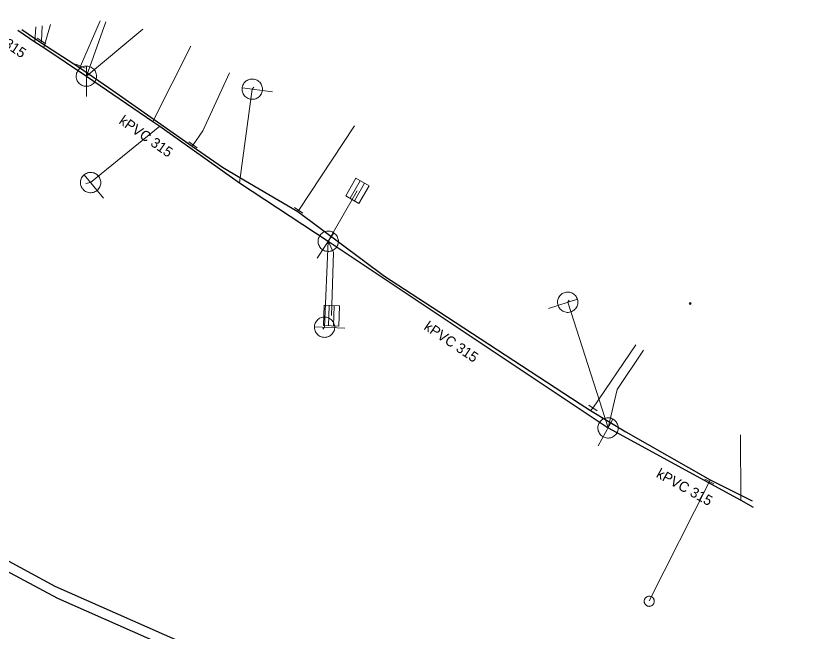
# Model space of a CAD drawing. Extents: x -783064 to -782702, y -1007904 to -1007145.
# Drawn here: x -782859.9 to -782780.5, y -1007215.4 to -1007154.7 of the extents above; entities that cross this region are included whole.
import ezdxf

# ---------------------------------------------------------------- set-up
doc = ezdxf.new("R2010")
doc.units = 0
doc.header["$LTSCALE"] = 0.4
doc.header["$PDMODE"] = 32
doc.header["$PDSIZE"] = 0.2
for name, color, linetype, lineweight in [('1', 7, 'Continuous', 13), ('11', 7, 'Continuous', 13), ('13', 7, 'Continuous', 13), ('14', 7, 'Continuous', 13), ('17', 7, 'Continuous', 25), ('22', 7, 'Continuous', 13), ('23', 7, 'Continuous', 13), ('34', 7, 'Continuous', 13)]:
    doc.layers.add(name, color=color, linetype=linetype, lineweight=lineweight)

msp = doc.modelspace()

# ---------------------------------------------------------------- linework, layer by layer
at = {"layer": '1'}
msp.add_point((-782793.51, -1007183.009), dxfattribs=at)
at = {"layer": '11'}
for p, q in [((-782851.068, -1007155.243), (-782852.989, -1007160.6)), ((-782857.952, -1007155.75), (-782858.07, -1007157.21)), ((-782856.506, -1007155.499), (-782857.17, -1007157.77)), ((-782847.429, -1007155.953), (-782852.989, -1007160.6)), ((-782842.69, -1007157.63), (-782846.434, -1007165.081)), ((-782836.5, -1007161.69), (-782836.647, -1007161.879)), ((-782836.647, -1007161.879), (-782837.899, -1007171.13)), ((-782852.569, -1007171.09), (-782845.765, -1007165.537)), ((-782853.039, -1007171.19), (-782852.569, -1007171.09)), ((-782826.307, -1007171.904), (-782829.169, -1007176.88)), ((-782829.529, -1007185.35), (-782829.169, -1007176.88)), ((-782805.43, -1007182.7), (-782805.579, -1007182.886)), ((-782805.579, -1007182.886), (-782801.609, -1007195.279)), ((-782829.704, -1007185.555), (-782829.529, -1007185.35)), ((-782788.567, -1007195.961), (-782788.533, -1007202.406))]:
    msp.add_line(p, q, dxfattribs=at)
for points in [[(-782828.847, -1007184.207), (-782828.635, -1007177.99), (-782829.169, -1007176.88)], [(-782798.12, -1007187.6), (-782800.719, -1007191.48), (-782801.609, -1007195.279)]]:
    msp.add_lwpolyline(points, dxfattribs=at)
at = {"layer": '13'}
for p, q in [((-782853.579, -1007159.609), (-782851.617, -1007155.136)), ((-782857.399, -1007157.139), (-782857.358, -1007155.647)), ((-782832.07, -1007173.819), (-782826.57, -1007165.49)), ((-782803.099, -1007193.329), (-782798.879, -1007187.09)), ((-782791.62, -1007200.559), (-782797.559, -1007212.339))]:
    msp.add_line(p, q, dxfattribs=at)
msp.add_lwpolyline([(-782842.472, -1007167.376), (-782841.51, -1007166), (-782838.899, -1007160.26)], dxfattribs=at)
at = {"layer": '14'}
for p, q in [((-782857.48, -1007157.266), (-782857.399, -1007157.139)), ((-782853.666, -1007159.732), (-782853.579, -1007159.609)), ((-782842.559, -1007167.5), (-782842.472, -1007167.376)), ((-782832.151, -1007173.945), (-782832.07, -1007173.819)), ((-782803.32, -1007193.55), (-782803.099, -1007193.329)), ((-782791.539, -1007200.39), (-782791.62, -1007200.559))]:
    msp.add_line(p, q, dxfattribs=at)
at = {"layer": '14', "lineweight": 25}
msp.add_line((-782829.169, -1007176.88), (-782801.609, -1007195.279), dxfattribs=at)
for points in [[(-782859.737, -1007156.06), (-782858.07, -1007157.21), (-782857.17, -1007157.77), (-782852.989, -1007160.6)], [(-782852.989, -1007160.6), (-782846.434, -1007165.081), (-782845.765, -1007165.537), (-782837.899, -1007171.13), (-782829.169, -1007176.88)], [(-782801.609, -1007195.279), (-782788.533, -1007202.406), (-782787.302, -1007203.076)]]:
    msp.add_lwpolyline(points, dxfattribs=at)
at = {"layer": '17'}
for points in [[(-782859.332, -1007155.99), (-782857.48, -1007157.266), (-782853.666, -1007159.732), (-782850.388, -1007162.024), (-782842.559, -1007167.5), (-782839.596, -1007169.572), (-782837.872, -1007170.585), (-782832.151, -1007173.945), (-782823.609, -1007180.33), (-782818.278, -1007183.806), (-782804.359, -1007192.92), (-782803.32, -1007193.55), (-782799.87, -1007195.68), (-782791.539, -1007200.39), (-782787.409, -1007202.472)], [(-782780.739, -1007239.982), (-782822.337, -1007225.824), (-782856.072, -1007210.901), (-782877.582, -1007199.233), (-782894.804, -1007187.137)], [(-782894.804, -1007187.137), (-782878.263, -1007200.064), (-782855.822, -1007212.077), (-782822.195, -1007226.94), (-782780.544, -1007241.082)]]:
    msp.add_lwpolyline(points, dxfattribs=at)
at = {"layer": '22'}
for p, q in [((-782852.989, -1007162.6), (-782852.988, -1007159.6)), ((-782834.664, -1007162.147), (-782837.637, -1007161.744)), ((-782851.304, -1007172.639), (-782853.2, -1007170.315)), ((-782826.013, -1007170.906), (-782827.011, -1007172.639)), ((-782825.58, -1007171.155), (-782826.577, -1007172.889)), ((-782830.269, -1007178.55), (-782828.619, -1007176.045)), ((-782807.484, -1007183.496), (-782804.627, -1007182.581)), ((-782829.137, -1007185.208), (-782829.069, -1007183.209)), ((-782828.638, -1007185.225), (-782828.569, -1007183.226)), ((-782827.53, -1007185.434), (-782830.527, -1007185.307)), ((-782802.566, -1007197.035), (-782801.13, -1007194.401))]:
    msp.add_line(p, q, dxfattribs=at)
for points in [[(-782851.989, -1007160.6), (-782851.994, -1007160.491), (-782852.012, -1007160.383), (-782852.042, -1007160.277), (-782852.082, -1007160.176), (-782852.134, -1007160.079), (-782852.196, -1007159.989), (-782852.268, -1007159.906), (-782852.348, -1007159.832), (-782852.436, -1007159.766), (-782852.53, -1007159.711), (-782852.63, -1007159.666), (-782852.735, -1007159.633), (-782852.842, -1007159.611), (-782852.951, -1007159.601), (-782853.061, -1007159.603), (-782853.169, -1007159.617), (-782853.276, -1007159.642), (-782853.379, -1007159.679), (-782853.477, -1007159.728), (-782853.569, -1007159.786), (-782853.655, -1007159.855), (-782853.732, -1007159.932), (-782853.801, -1007160.018), (-782853.86, -1007160.11), (-782853.908, -1007160.208), (-782853.945, -1007160.311), (-782853.971, -1007160.418), (-782853.985, -1007160.526), (-782853.988, -1007160.636), (-782853.978, -1007160.745), (-782853.957, -1007160.852), (-782853.923, -1007160.956), (-782853.879, -1007161.056), (-782853.824, -1007161.151), (-782853.758, -1007161.239), (-782853.684, -1007161.319), (-782853.601, -1007161.391), (-782853.511, -1007161.453), (-782853.415, -1007161.505), (-782853.313, -1007161.546), (-782853.208, -1007161.576), (-782853.1, -1007161.594), (-782852.99, -1007161.6), (-782852.881, -1007161.594), (-782852.773, -1007161.576), (-782852.668, -1007161.547), (-782852.566, -1007161.506), (-782852.469, -1007161.454), (-782852.379, -1007161.392), (-782852.296, -1007161.321), (-782852.221, -1007161.241), (-782852.156, -1007161.153), (-782852.1, -1007161.059), (-782852.056, -1007160.959), (-782852.022, -1007160.855), (-782852, -1007160.747), (-782851.99, -1007160.638)], [(-782836.512, -1007160.888), (-782836.621, -1007160.879), (-782836.73, -1007160.882), (-782836.839, -1007160.898), (-782836.945, -1007160.924), (-782837.048, -1007160.962), (-782837.145, -1007161.012), (-782837.237, -1007161.072), (-782837.321, -1007161.141), (-782837.398, -1007161.22), (-782837.466, -1007161.305), (-782837.524, -1007161.399), (-782837.57, -1007161.498), (-782837.606, -1007161.601), (-782837.631, -1007161.708), (-782837.644, -1007161.817), (-782837.644, -1007161.926), (-782837.634, -1007162.035), (-782837.611, -1007162.143), (-782837.576, -1007162.246), (-782837.531, -1007162.345), (-782837.474, -1007162.44), (-782837.408, -1007162.526), (-782837.332, -1007162.606), (-782837.249, -1007162.677), (-782837.158, -1007162.738), (-782837.061, -1007162.788), (-782836.958, -1007162.828), (-782836.853, -1007162.857), (-782836.744, -1007162.873), (-782836.635, -1007162.878), (-782836.526, -1007162.872), (-782836.418, -1007162.852), (-782836.313, -1007162.822), (-782836.212, -1007162.78), (-782836.116, -1007162.726), (-782836.027, -1007162.664), (-782835.944, -1007162.591), (-782835.871, -1007162.51), (-782835.806, -1007162.422), (-782835.752, -1007162.327), (-782835.708, -1007162.226), (-782835.676, -1007162.122), (-782835.655, -1007162.014), (-782835.646, -1007161.905), (-782835.65, -1007161.795), (-782835.665, -1007161.687), (-782835.691, -1007161.581), (-782835.73, -1007161.478), (-782835.779, -1007161.38), (-782835.839, -1007161.289), (-782835.908, -1007161.203), (-782835.986, -1007161.127), (-782836.072, -1007161.059), (-782836.165, -1007161.002), (-782836.264, -1007160.954), (-782836.368, -1007160.918), (-782836.474, -1007160.894)], [(-782851.793, -1007170.458), (-782851.867, -1007170.377), (-782851.949, -1007170.305), (-782852.04, -1007170.242), (-782852.134, -1007170.189), (-782852.236, -1007170.146), (-782852.341, -1007170.116), (-782852.449, -1007170.097), (-782852.558, -1007170.09), (-782852.668, -1007170.095), (-782852.775, -1007170.112), (-782852.881, -1007170.14), (-782852.984, -1007170.181), (-782853.08, -1007170.231), (-782853.171, -1007170.293), (-782853.255, -1007170.364), (-782853.33, -1007170.443), (-782853.397, -1007170.53), (-782853.453, -1007170.624), (-782853.498, -1007170.724), (-782853.533, -1007170.827), (-782853.556, -1007170.934), (-782853.567, -1007171.043), (-782853.566, -1007171.153), (-782853.554, -1007171.262), (-782853.529, -1007171.368), (-782853.492, -1007171.471), (-782853.445, -1007171.57), (-782853.387, -1007171.663), (-782853.319, -1007171.749), (-782853.243, -1007171.828), (-782853.159, -1007171.897), (-782853.067, -1007171.956), (-782852.969, -1007172.006), (-782852.867, -1007172.045), (-782852.76, -1007172.071), (-782852.652, -1007172.086), (-782852.542, -1007172.09), (-782852.433, -1007172.081), (-782852.326, -1007172.06), (-782852.221, -1007172.028), (-782852.121, -1007171.984), (-782852.026, -1007171.93), (-782851.937, -1007171.865), (-782851.856, -1007171.792), (-782851.784, -1007171.709), (-782851.721, -1007171.621), (-782851.668, -1007171.524), (-782851.625, -1007171.423), (-782851.595, -1007171.318), (-782851.575, -1007171.21), (-782851.568, -1007171.101), (-782851.573, -1007170.992), (-782851.589, -1007170.883), (-782851.618, -1007170.778), (-782851.658, -1007170.676), (-782851.709, -1007170.578), (-782851.77, -1007170.488)], [(-782825.147, -1007171.404), (-782826.144, -1007173.138), (-782827.444, -1007172.39), (-782826.447, -1007170.656)], [(-782828.334, -1007177.43), (-782828.279, -1007177.336), (-782828.234, -1007177.236), (-782828.201, -1007177.131), (-782828.179, -1007177.024), (-782828.169, -1007176.915), (-782828.171, -1007176.805), (-782828.186, -1007176.696), (-782828.212, -1007176.591), (-782828.249, -1007176.487), (-782828.297, -1007176.389), (-782828.356, -1007176.297), (-782828.426, -1007176.212), (-782828.503, -1007176.134), (-782828.588, -1007176.066), (-782828.681, -1007176.007), (-782828.779, -1007175.959), (-782828.882, -1007175.921), (-782828.989, -1007175.896), (-782829.098, -1007175.883), (-782829.206, -1007175.881), (-782829.316, -1007175.891), (-782829.423, -1007175.913), (-782829.528, -1007175.947), (-782829.627, -1007175.991), (-782829.721, -1007176.046), (-782829.809, -1007176.112), (-782829.89, -1007176.187), (-782829.961, -1007176.27), (-782830.023, -1007176.36), (-782830.074, -1007176.457), (-782830.116, -1007176.558), (-782830.145, -1007176.663), (-782830.163, -1007176.771), (-782830.169, -1007176.881), (-782830.162, -1007176.991), (-782830.145, -1007177.098), (-782830.115, -1007177.204), (-782830.074, -1007177.305), (-782830.022, -1007177.401), (-782829.96, -1007177.492), (-782829.889, -1007177.575), (-782829.808, -1007177.649), (-782829.72, -1007177.714), (-782829.625, -1007177.769), (-782829.525, -1007177.814), (-782829.422, -1007177.847), (-782829.314, -1007177.869), (-782829.204, -1007177.879), (-782829.095, -1007177.877), (-782828.987, -1007177.863), (-782828.88, -1007177.838), (-782828.777, -1007177.8), (-782828.679, -1007177.752), (-782828.587, -1007177.693), (-782828.501, -1007177.625), (-782828.424, -1007177.547), (-782828.355, -1007177.461)], [(-782805.274, -1007183.838), (-782805.172, -1007183.799), (-782805.075, -1007183.749), (-782804.983, -1007183.688), (-782804.899, -1007183.619), (-782804.822, -1007183.54), (-782804.755, -1007183.454), (-782804.698, -1007183.36), (-782804.652, -1007183.261), (-782804.616, -1007183.157), (-782804.593, -1007183.051), (-782804.58, -1007182.942), (-782804.581, -1007182.832), (-782804.593, -1007182.723), (-782804.616, -1007182.616), (-782804.652, -1007182.512), (-782804.698, -1007182.413), (-782804.755, -1007182.319), (-782804.821, -1007182.232), (-782804.898, -1007182.154), (-782804.981, -1007182.084), (-782805.073, -1007182.023), (-782805.17, -1007181.973), (-782805.273, -1007181.934), (-782805.378, -1007181.906), (-782805.486, -1007181.89), (-782805.596, -1007181.886), (-782805.706, -1007181.894), (-782805.813, -1007181.914), (-782805.918, -1007181.945), (-782806.019, -1007181.988), (-782806.114, -1007182.041), (-782806.203, -1007182.105), (-782806.285, -1007182.177), (-782806.358, -1007182.259), (-782806.422, -1007182.348), (-782806.476, -1007182.443), (-782806.519, -1007182.544), (-782806.551, -1007182.649), (-782806.571, -1007182.756), (-782806.579, -1007182.866), (-782806.575, -1007182.975), (-782806.559, -1007183.083), (-782806.532, -1007183.19), (-782806.493, -1007183.292), (-782806.443, -1007183.389), (-782806.383, -1007183.48), (-782806.313, -1007183.565), (-782806.234, -1007183.641), (-782806.147, -1007183.708), (-782806.054, -1007183.766), (-782805.955, -1007183.813), (-782805.851, -1007183.848), (-782805.745, -1007183.872), (-782805.636, -1007183.884), (-782805.527, -1007183.884), (-782805.417, -1007183.872), (-782805.31, -1007183.849)], [(-782829.637, -1007185.191), (-782829.569, -1007183.192), (-782828.07, -1007183.243), (-782828.138, -1007185.242)], [(-782829.486, -1007184.35), (-782829.595, -1007184.352), (-782829.703, -1007184.365), (-782829.811, -1007184.391), (-782829.913, -1007184.426), (-782830.012, -1007184.474), (-782830.105, -1007184.532), (-782830.191, -1007184.601), (-782830.268, -1007184.677), (-782830.338, -1007184.763), (-782830.397, -1007184.854), (-782830.446, -1007184.952), (-782830.483, -1007185.056), (-782830.51, -1007185.162), (-782830.525, -1007185.27), (-782830.527, -1007185.38), (-782830.518, -1007185.489), (-782830.497, -1007185.597), (-782830.465, -1007185.701), (-782830.42, -1007185.801), (-782830.366, -1007185.895), (-782830.301, -1007185.984), (-782830.227, -1007186.064), (-782830.144, -1007186.137), (-782830.055, -1007186.2), (-782829.959, -1007186.252), (-782829.857, -1007186.293), (-782829.752, -1007186.324), (-782829.644, -1007186.342), (-782829.534, -1007186.349), (-782829.425, -1007186.344), (-782829.317, -1007186.327), (-782829.212, -1007186.298), (-782829.11, -1007186.258), (-782829.013, -1007186.207), (-782828.922, -1007186.145), (-782828.839, -1007186.074), (-782828.764, -1007185.995), (-782828.698, -1007185.907), (-782828.642, -1007185.814), (-782828.597, -1007185.713), (-782828.562, -1007185.61), (-782828.54, -1007185.503), (-782828.529, -1007185.393), (-782828.53, -1007185.284), (-782828.544, -1007185.175), (-782828.568, -1007185.069), (-782828.605, -1007184.965), (-782828.653, -1007184.866), (-782828.711, -1007184.774), (-782828.778, -1007184.688), (-782828.855, -1007184.609), (-782828.94, -1007184.541), (-782829.032, -1007184.481), (-782829.13, -1007184.433), (-782829.232, -1007184.394), (-782829.339, -1007184.368), (-782829.448, -1007184.353)], [(-782800.731, -1007195.757), (-782800.684, -1007195.659), (-782800.648, -1007195.555), (-782800.624, -1007195.448), (-782800.61, -1007195.34), (-782800.61, -1007195.23), (-782800.621, -1007195.121), (-782800.644, -1007195.014), (-782800.679, -1007194.911), (-782800.725, -1007194.811), (-782800.781, -1007194.717), (-782800.847, -1007194.63), (-782800.924, -1007194.551), (-782801.007, -1007194.48), (-782801.098, -1007194.419), (-782801.196, -1007194.369), (-782801.297, -1007194.329), (-782801.403, -1007194.3), (-782801.511, -1007194.283), (-782801.621, -1007194.279), (-782801.729, -1007194.286), (-782801.838, -1007194.306), (-782801.942, -1007194.336), (-782802.044, -1007194.379), (-782802.14, -1007194.431), (-782802.229, -1007194.495), (-782802.311, -1007194.567), (-782802.385, -1007194.649), (-782802.449, -1007194.737), (-782802.503, -1007194.833), (-782802.547, -1007194.933), (-782802.579, -1007195.037), (-782802.599, -1007195.145), (-782802.608, -1007195.253), (-782802.606, -1007195.363), (-782802.59, -1007195.472), (-782802.563, -1007195.578), (-782802.525, -1007195.681), (-782802.475, -1007195.778), (-782802.416, -1007195.87), (-782802.346, -1007195.955), (-782802.268, -1007196.031), (-782802.182, -1007196.099), (-782802.088, -1007196.157), (-782801.99, -1007196.203), (-782801.886, -1007196.239), (-782801.78, -1007196.264), (-782801.671, -1007196.277), (-782801.561, -1007196.278), (-782801.452, -1007196.266), (-782801.345, -1007196.244), (-782801.241, -1007196.209), (-782801.142, -1007196.163), (-782801.048, -1007196.107), (-782800.961, -1007196.041), (-782800.882, -1007195.966), (-782800.811, -1007195.881), (-782800.75, -1007195.79)]]:
    msp.add_lwpolyline(points, close=True, dxfattribs=at)
at = {"layer": '23'}
for points in [[(-782797.328, -1007211.92), (-782797.377, -1007211.899), (-782797.427, -1007211.884), (-782797.478, -1007211.875), (-782797.53, -1007211.87), (-782797.582, -1007211.871), (-782797.635, -1007211.878), (-782797.685, -1007211.889), (-782797.734, -1007211.906), (-782797.782, -1007211.928), (-782797.827, -1007211.955), (-782797.869, -1007211.986), (-782797.908, -1007212.022), (-782797.942, -1007212.061), (-782797.971, -1007212.103), (-782797.997, -1007212.149), (-782798.018, -1007212.199), (-782798.034, -1007212.247), (-782798.044, -1007212.3), (-782798.049, -1007212.35), (-782798.048, -1007212.403), (-782798.041, -1007212.456), (-782798.029, -1007212.507), (-782798.012, -1007212.557), (-782797.991, -1007212.604), (-782797.964, -1007212.648), (-782797.931, -1007212.69), (-782797.897, -1007212.728), (-782797.857, -1007212.763), (-782797.814, -1007212.792), (-782797.769, -1007212.818), (-782797.721, -1007212.839), (-782797.67, -1007212.854), (-782797.618, -1007212.865), (-782797.567, -1007212.87), (-782797.516, -1007212.867), (-782797.463, -1007212.861), (-782797.412, -1007212.85), (-782797.362, -1007212.833), (-782797.315, -1007212.811)], [(-782798.044, -1007212.3), (-782798.049, -1007212.35), (-782798.048, -1007212.403), (-782798.041, -1007212.456), (-782798.029, -1007212.507), (-782798.012, -1007212.557), (-782797.991, -1007212.604), (-782797.964, -1007212.648), (-782797.931, -1007212.69), (-782797.897, -1007212.728), (-782797.857, -1007212.763), (-782797.814, -1007212.792), (-782797.769, -1007212.818), (-782797.721, -1007212.839), (-782797.67, -1007212.854), (-782797.618, -1007212.865), (-782797.567, -1007212.87), (-782797.516, -1007212.867), (-782797.463, -1007212.861), (-782797.412, -1007212.85), (-782797.362, -1007212.833), (-782797.315, -1007212.811), (-782797.27, -1007212.785), (-782797.228, -1007212.753), (-782797.189, -1007212.718), (-782797.155, -1007212.677), (-782797.126, -1007212.635), (-782797.1, -1007212.59), (-782797.08, -1007212.542), (-782797.064, -1007212.492), (-782797.053, -1007212.44), (-782797.05, -1007212.388), (-782797.05, -1007212.335), (-782797.056, -1007212.284), (-782797.069, -1007212.233), (-782797.084, -1007212.183), (-782797.107, -1007212.136), (-782797.134, -1007212.09), (-782797.165, -1007212.048), (-782797.201, -1007212.01)], [(-782797.315, -1007212.811), (-782797.27, -1007212.785), (-782797.228, -1007212.753), (-782797.189, -1007212.718), (-782797.155, -1007212.677), (-782797.126, -1007212.635), (-782797.1, -1007212.59), (-782797.08, -1007212.542), (-782797.064, -1007212.492), (-782797.053, -1007212.44), (-782797.05, -1007212.388), (-782797.05, -1007212.335), (-782797.056, -1007212.284), (-782797.069, -1007212.233), (-782797.084, -1007212.183), (-782797.107, -1007212.136), (-782797.134, -1007212.09), (-782797.165, -1007212.048), (-782797.201, -1007212.01), (-782797.241, -1007211.977), (-782797.283, -1007211.947), (-782797.328, -1007211.92), (-782797.377, -1007211.899), (-782797.427, -1007211.884), (-782797.478, -1007211.875), (-782797.53, -1007211.87), (-782797.582, -1007211.871), (-782797.635, -1007211.878), (-782797.685, -1007211.889), (-782797.734, -1007211.906), (-782797.782, -1007211.928), (-782797.827, -1007211.955), (-782797.869, -1007211.986), (-782797.908, -1007212.022), (-782797.942, -1007212.061), (-782797.971, -1007212.103), (-782797.997, -1007212.149), (-782798.018, -1007212.199), (-782798.034, -1007212.247), (-782798.044, -1007212.3)], [(-782797.201, -1007212.01), (-782797.241, -1007211.977), (-782797.283, -1007211.947), (-782797.328, -1007211.92)]]:
    msp.add_lwpolyline(points, dxfattribs=at)
at = {"layer": '34'}
for p, q in [((-782857.819, -1007156.869), (-782856.978, -1007157.409)), ((-782854.037, -1007159.408), (-782853.121, -1007159.81)), ((-782842.882, -1007167.089), (-782842.062, -1007167.662)), ((-782832.487, -1007173.543), (-782831.653, -1007174.094)), ((-782803.513, -1007193.049), (-782802.685, -1007193.609)), ((-782792.066, -1007200.334), (-782791.173, -1007200.784))]:
    msp.add_line(p, q, dxfattribs=at)

# ---------------------------------------------------------------- texts
at = {"layer": '1'}
for rotation, p in [(326, (-782864.348, -1007155.5)), (325, (-782849.86, -1007165.203)), (326, (-782819.818, -1007185.509)), (331, (-782796.941, -1007200.084))]:
    msp.add_text('kPVC 315', height=1, rotation=rotation, dxfattribs=at).set_placement(p)

doc.saveas('drawing.dxf')
